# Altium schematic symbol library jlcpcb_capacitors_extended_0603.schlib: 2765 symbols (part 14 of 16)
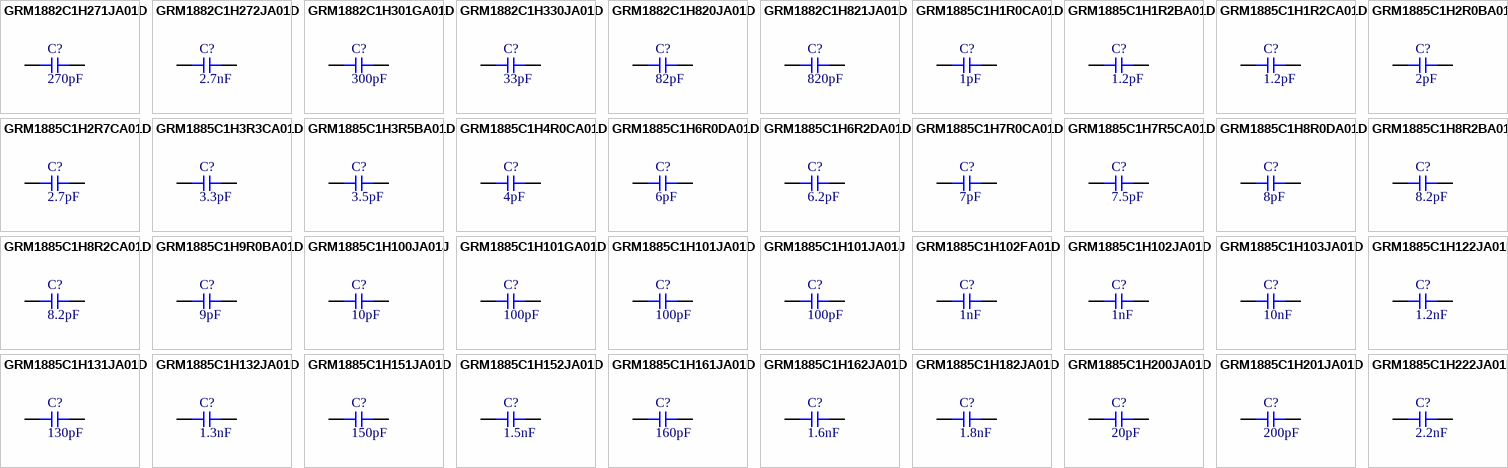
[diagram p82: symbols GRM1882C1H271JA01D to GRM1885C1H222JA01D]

## GRM1885C1H8R0DA01D
designator C?  Capacitance: 8pF  (hidden comment: *)
Capacitor, Ceramic (MLCC), 8pF, ±0.5pF, 50V, C0G, ±0.5pF, SMD 0603; Manufacturer: Murata Electronics; Manufacturer Part Number: GRM1885C1H8R0DA01D
footprint CAP-0603 (0603 (1608M) Capacitor)
pins: 1, 2

## GRM1885C1H8R2BA01D
designator C?  Capacitance: 8.2pF  (hidden comment: *)
Capacitor, Ceramic (MLCC), 8.2pF, ±0.1pF, 50V, ±0.1pF, SMD 0603; Manufacturer: Murata Electronics; Manufacturer Part Number: GRM1885C1H8R2BA01D
footprint CAP-0603 (0603 (1608M) Capacitor)
pins: 1, 2

## GRM1885C1H8R2CA01D
designator C?  Capacitance: 8.2pF  (hidden comment: *)
Capacitor, Ceramic (MLCC), 8.2pF, ±0.25pF, 50V, C0G, ±0.25pF, SMD 0603; Manufacturer: Murata Electronics; Manufacturer Part Number: GRM1885C1H8R2CA01D
footprint CAP-0603 (0603 (1608M) Capacitor)
pins: 1, 2

## GRM1885C1H9R0BA01D
designator C?  Capacitance: 9pF  (hidden comment: *)
Capacitor, Ceramic (MLCC), 9pF, ±0.1pF, 50V, C0G, ±0.1pF, SMD 0603; Manufacturer: Murata Electronics; Manufacturer Part Number: GRM1885C1H9R0BA01D
footprint CAP-0603 (0603 (1608M) Capacitor)
pins: 1, 2

## GRM1885C1H100JA01J
designator C?  Capacitance: 10pF  (hidden comment: *)
Capacitor, Ceramic (MLCC), 10pF, ±5%, 50V, C0G, ±5%, SMD 0603; Manufacturer: Murata Electronics; Manufacturer Part Number: GRM1885C1H100JA01J
footprint CAP-0603 (0603 (1608M) Capacitor)
pins: 1, 2

## GRM1885C1H101GA01D
designator C?  Capacitance: 100pF  (hidden comment: *)
Capacitor, Ceramic (MLCC), 100pF, ±2%, ±2%, SMD 0603; Manufacturer: Murata Electronics; Manufacturer Part Number: GRM1885C1H101GA01D
footprint CAP-0603 (0603 (1608M) Capacitor)
pins: 1, 2

## GRM1885C1H101JA01D
designator C?  Capacitance: 100pF  (hidden comment: *)
Capacitor, Ceramic (MLCC), 100pF, ±5%, 50V, C0G, ±5%, SMD 0603; Manufacturer: Murata Electronics; Manufacturer Part Number: GRM1885C1H101JA01D
footprint CAP-0603 (0603 (1608M) Capacitor)
pins: 1, 2

## GRM1885C1H101JA01J
designator C?  Capacitance: 100pF  (hidden comment: *)
Capacitor, Ceramic (MLCC), 100pF, ±5%, 50V, C0G, ±5%, SMD 0603; Manufacturer: Murata Electronics; Manufacturer Part Number: GRM1885C1H101JA01J
footprint CAP-0603 (0603 (1608M) Capacitor)
pins: 1, 2

## GRM1885C1H102FA01D
designator C?  Capacitance: 1nF  (hidden comment: *)
Capacitor, Ceramic (MLCC), 1nF, ±1%, ±1%, SMD 0603; Manufacturer: Murata Electronics; Manufacturer Part Number: GRM1885C1H102FA01D
footprint CAP-0603 (0603 (1608M) Capacitor)
pins: 1, 2

## GRM1885C1H102JA01D
designator C?  Capacitance: 1nF  (hidden comment: *)
Capacitor, Ceramic (MLCC), 1nF, ±5%, 50V, C0G, ±5%, SMD 0603; Manufacturer: Murata Electronics; Manufacturer Part Number: GRM1885C1H102JA01D
footprint CAP-0603 (0603 (1608M) Capacitor)
pins: 1, 2

## GRM1885C1H103JA01D
designator C?  Capacitance: 10nF  (hidden comment: *)
Capacitor, Ceramic (MLCC), 10nF, ±5%, 50V, C0G, ±5%, SMD 0603; Manufacturer: Murata Electronics; Manufacturer Part Number: GRM1885C1H103JA01D
footprint CAP-0603 (0603 (1608M) Capacitor)
pins: 1, 2

## GRM1885C1H122JA01D
designator C?  Capacitance: 1.2nF  (hidden comment: *)
Capacitor, Ceramic (MLCC), 1.2nF, ±5%, 50V, C0G, ±5%, SMD 0603; Manufacturer: Murata Electronics; Manufacturer Part Number: GRM1885C1H122JA01D
footprint CAP-0603 (0603 (1608M) Capacitor)
pins: 1, 2

## GRM1885C1H131JA01D
designator C?  Capacitance: 130pF  (hidden comment: *)
Capacitor, Ceramic (MLCC), 130pF, ±5%, 50V, C0G, ±5%, SMD 0603; Manufacturer: Murata Electronics; Manufacturer Part Number: GRM1885C1H131JA01D
footprint CAP-0603 (0603 (1608M) Capacitor)
pins: 1, 2

## GRM1885C1H132JA01D
designator C?  Capacitance: 1.3nF  (hidden comment: *)
Capacitor, Ceramic (MLCC), 1.3nF, ±5%, 50V, ±5%, SMD 0603; Manufacturer: Murata Electronics; Manufacturer Part Number: GRM1885C1H132JA01D
footprint CAP-0603 (0603 (1608M) Capacitor)
pins: 1, 2

## GRM1885C1H151JA01D
designator C?  Capacitance: 150pF  (hidden comment: *)
Capacitor, Ceramic (MLCC), 150pF, ±5%, 50V, C0G, ±5%, SMD 0603; Manufacturer: Murata Electronics; Manufacturer Part Number: GRM1885C1H151JA01D
footprint CAP-0603 (0603 (1608M) Capacitor)
pins: 1, 2

## GRM1885C1H152JA01D
designator C?  Capacitance: 1.5nF  (hidden comment: *)
Capacitor, Ceramic (MLCC), 1.5nF, ±5%, 50V, C0G, ±5%, SMD 0603; Manufacturer: Murata Electronics; Manufacturer Part Number: GRM1885C1H152JA01D
footprint CAP-0603 (0603 (1608M) Capacitor)
pins: 1, 2

## GRM1885C1H161JA01D
designator C?  Capacitance: 160pF  (hidden comment: *)
Capacitor, Ceramic (MLCC), 160pF, ±5%, ±5%, SMD 0603; Manufacturer: Murata Electronics; Manufacturer Part Number: GRM1885C1H161JA01D
footprint CAP-0603 (0603 (1608M) Capacitor)
pins: 1, 2

## GRM1885C1H162JA01D
designator C?  Capacitance: 1.6nF  (hidden comment: *)
Capacitor, Ceramic (MLCC), 1.6nF, ±5%, 50V, C0G, ±5%, SMD 0603; Manufacturer: Murata Electronics; Manufacturer Part Number: GRM1885C1H162JA01D
footprint CAP-0603 (0603 (1608M) Capacitor)
pins: 1, 2

## GRM1885C1H182JA01D
designator C?  Capacitance: 1.8nF  (hidden comment: *)
Capacitor, Ceramic (MLCC), 1.8nF, ±5%, 50V, C0G, ±5%, SMD 0603; Manufacturer: Murata Electronics; Manufacturer Part Number: GRM1885C1H182JA01D
footprint CAP-0603 (0603 (1608M) Capacitor)
pins: 1, 2

## GRM1885C1H200JA01D
designator C?  Capacitance: 20pF  (hidden comment: *)
Capacitor, Ceramic (MLCC), 20pF, ±5%, 50V, C0G, ±5%, SMD 0603; Manufacturer: Murata Electronics; Manufacturer Part Number: GRM1885C1H200JA01D
footprint CAP-0603 (0603 (1608M) Capacitor)
pins: 1, 2

## GRM1885C1H201JA01D
designator C?  Capacitance: 200pF  (hidden comment: *)
Capacitor, Ceramic (MLCC), 200pF, ±5%, 50V, C0G, ±5%, SMD 0603; Manufacturer: Murata Electronics; Manufacturer Part Number: GRM1885C1H201JA01D
footprint CAP-0603 (0603 (1608M) Capacitor)
pins: 1, 2

## GRM1885C1H222JA01D
designator C?  Capacitance: 2.2nF  (hidden comment: *)
Capacitor, Ceramic (MLCC), 2.2nF, ±5%, 50V, C0G, ±5%, SMD 0603; Manufacturer: Murata Electronics; Manufacturer Part Number: GRM1885C1H222JA01D
footprint CAP-0603 (0603 (1608M) Capacitor)
pins: 1, 2

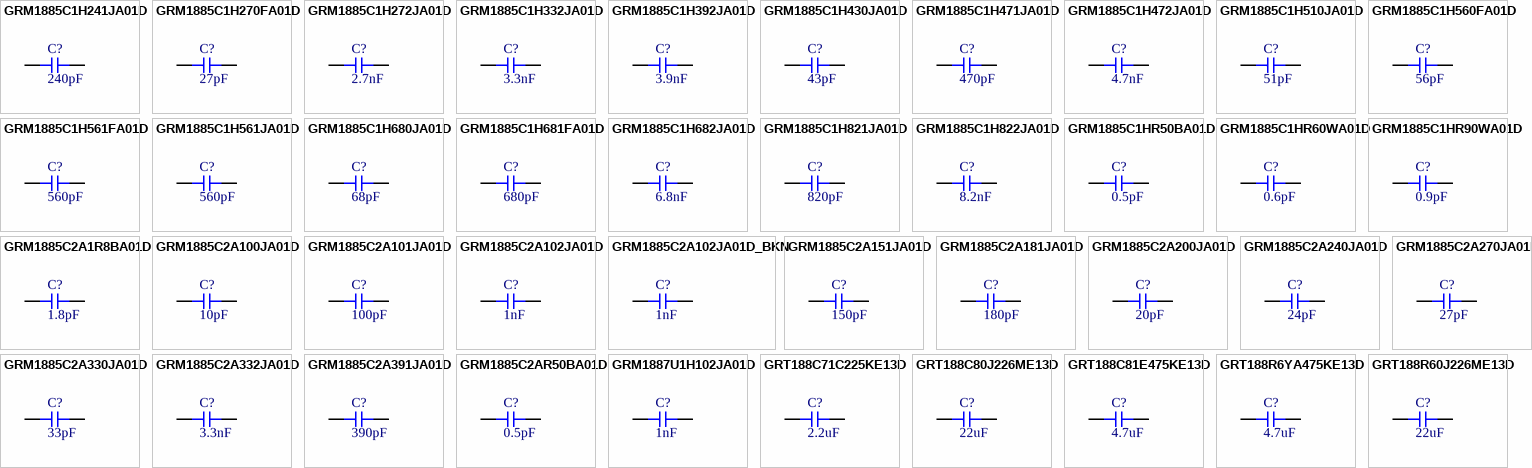
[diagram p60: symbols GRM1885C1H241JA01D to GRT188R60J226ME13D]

## GRM1885C1H241JA01D
designator C?  Capacitance: 240pF  (hidden comment: *)
Capacitor, Ceramic (MLCC), 240pF, ±5%, 50V, C0G, ±5%, SMD 0603; Manufacturer: Murata Electronics; Manufacturer Part Number: GRM1885C1H241JA01D
footprint CAP-0603 (0603 (1608M) Capacitor)
pins: 1, 2

## GRM1885C1H270FA01D
designator C?  Capacitance: 27pF  (hidden comment: *)
Capacitor, Ceramic (MLCC), 27pF, ±1%, 50V, C0G, ±1%, SMD 0603; Manufacturer: Murata Electronics; Manufacturer Part Number: GRM1885C1H270FA01D
footprint CAP-0603 (0603 (1608M) Capacitor)
pins: 1, 2

## GRM1885C1H272JA01D
designator C?  Capacitance: 2.7nF  (hidden comment: *)
Capacitor, Ceramic (MLCC), 2.7nF, ±5%, 50V, C0G, ±5%, SMD 0603; Manufacturer: Murata Electronics; Manufacturer Part Number: GRM1885C1H272JA01D
footprint CAP-0603 (0603 (1608M) Capacitor)
pins: 1, 2

## GRM1885C1H332JA01D
designator C?  Capacitance: 3.3nF  (hidden comment: *)
Capacitor, Ceramic (MLCC), 3.3nF, ±5%, 50V, C0G, ±5%, SMD 0603; Manufacturer: Murata Electronics; Manufacturer Part Number: GRM1885C1H332JA01D
footprint CAP-0603 (0603 (1608M) Capacitor)
pins: 1, 2

## GRM1885C1H392JA01D
designator C?  Capacitance: 3.9nF  (hidden comment: *)
Capacitor, Ceramic (MLCC), 3.9nF, ±5%, 50V, C0G, ±5%, SMD 0603; Manufacturer: Murata Electronics; Manufacturer Part Number: GRM1885C1H392JA01D
footprint CAP-0603 (0603 (1608M) Capacitor)
pins: 1, 2

## GRM1885C1H430JA01D
designator C?  Capacitance: 43pF  (hidden comment: *)
Capacitor, Ceramic (MLCC), 43pF, ±5%, 50V, C0G, ±5%, SMD 0603; Manufacturer: Murata Electronics; Manufacturer Part Number: GRM1885C1H430JA01D
footprint CAP-0603 (0603 (1608M) Capacitor)
pins: 1, 2

## GRM1885C1H471JA01D
designator C?  Capacitance: 470pF  (hidden comment: *)
Capacitor, Ceramic (MLCC), 470pF, ±5%, 50V, C0G, ±5%, SMD 0603; Manufacturer: Murata Electronics; Manufacturer Part Number: GRM1885C1H471JA01D
footprint CAP-0603 (0603 (1608M) Capacitor)
pins: 1, 2

## GRM1885C1H472JA01D
designator C?  Capacitance: 4.7nF  (hidden comment: *)
Capacitor, Ceramic (MLCC), 4.7nF, ±5%, 50V, C0G, ±5%, SMD 0603; Manufacturer: Murata Electronics; Manufacturer Part Number: GRM1885C1H472JA01D
footprint CAP-0603 (0603 (1608M) Capacitor)
pins: 1, 2

## GRM1885C1H510JA01D
designator C?  Capacitance: 51pF  (hidden comment: *)
Capacitor, Ceramic (MLCC), 51pF, ±5%, 50V, C0G, ±5%, SMD 0603; Manufacturer: Murata Electronics; Manufacturer Part Number: GRM1885C1H510JA01D
footprint CAP-0603 (0603 (1608M) Capacitor)
pins: 1, 2

## GRM1885C1H560FA01D
designator C?  Capacitance: 56pF  (hidden comment: *)
Capacitor, Ceramic (MLCC), 56pF, ±1%, 50V, C0G, ±1%, SMD 0603; Manufacturer: Murata Electronics; Manufacturer Part Number: GRM1885C1H560FA01D
footprint CAP-0603 (0603 (1608M) Capacitor)
pins: 1, 2

## GRM1885C1H561FA01D
designator C?  Capacitance: 560pF  (hidden comment: *)
Capacitor, Ceramic (MLCC), 560pF, ±1%, 50V, C0G, ±1%, SMD 0603; Manufacturer: Murata Electronics; Manufacturer Part Number: GRM1885C1H561FA01D
footprint CAP-0603 (0603 (1608M) Capacitor)
pins: 1, 2

## GRM1885C1H561JA01D
designator C?  Capacitance: 560pF  (hidden comment: *)
Capacitor, Ceramic (MLCC), 560pF, ±5%, 50V, C0G, ±5%, SMD 0603; Manufacturer: Murata Electronics; Manufacturer Part Number: GRM1885C1H561JA01D
footprint CAP-0603 (0603 (1608M) Capacitor)
pins: 1, 2

## GRM1885C1H680JA01D
designator C?  Capacitance: 68pF  (hidden comment: *)
Capacitor, Ceramic (MLCC), 68pF, ±5%, 50V, C0G, ±5%, SMD 0603; Manufacturer: Murata Electronics; Manufacturer Part Number: GRM1885C1H680JA01D
footprint CAP-0603 (0603 (1608M) Capacitor)
pins: 1, 2

## GRM1885C1H681FA01D
designator C?  Capacitance: 680pF  (hidden comment: *)
Capacitor, Ceramic (MLCC), 680pF, ±1%, 50V, C0G, ±1%, SMD 0603; Manufacturer: Murata Electronics; Manufacturer Part Number: GRM1885C1H681FA01D
footprint CAP-0603 (0603 (1608M) Capacitor)
pins: 1, 2

## GRM1885C1H682JA01D
designator C?  Capacitance: 6.8nF  (hidden comment: *)
Capacitor, Ceramic (MLCC), 6.8nF, ±5%, 50V, C0G, ±5%, SMD 0603; Manufacturer: Murata Electronics; Manufacturer Part Number: GRM1885C1H682JA01D
footprint CAP-0603 (0603 (1608M) Capacitor)
pins: 1, 2

## GRM1885C1H821JA01D
designator C?  Capacitance: 820pF  (hidden comment: *)
Capacitor, Ceramic (MLCC), 820pF, ±5%, 50V, C0G, ±5%, SMD 0603; Manufacturer: Murata Electronics; Manufacturer Part Number: GRM1885C1H821JA01D
footprint CAP-0603 (0603 (1608M) Capacitor)
pins: 1, 2

## GRM1885C1H822JA01D
designator C?  Capacitance: 8.2nF  (hidden comment: *)
Capacitor, Ceramic (MLCC), 8.2nF, ±5%, 50V, ±5%, SMD 0603; Manufacturer: Murata Electronics; Manufacturer Part Number: GRM1885C1H822JA01D
footprint CAP-0603 (0603 (1608M) Capacitor)
pins: 1, 2

## GRM1885C1HR50BA01D
designator C?  Capacitance: 0.5pF  (hidden comment: *)
Capacitor, Ceramic (MLCC), 0.5pF, ±0.1pF, 50V, C0G, ±0.1pF, SMD 0603; Manufacturer: Murata Electronics; Manufacturer Part Number: GRM1885C1HR50BA01D
footprint CAP-0603 (0603 (1608M) Capacitor)
pins: 1, 2

## GRM1885C1HR60WA01D
designator C?  Capacitance: 0.6pF  (hidden comment: *)
Capacitor, Ceramic (MLCC), 0.6pF, ±0.05pF, 50V, C0G, ±0.05pF, SMD 0603; Manufacturer: Murata Electronics; Manufacturer Part Number: GRM1885C1HR60WA01D
footprint CAP-0603 (0603 (1608M) Capacitor)
pins: 1, 2

## GRM1885C1HR90WA01D
designator C?  Capacitance: 0.9pF  (hidden comment: *)
Capacitor, Ceramic (MLCC), 0.9pF, ±0.05pF, 50V, C0G, ±0.05pF, SMD 0603; Manufacturer: Murata Electronics; Manufacturer Part Number: GRM1885C1HR90WA01D
footprint CAP-0603 (0603 (1608M) Capacitor)
pins: 1, 2

## GRM1885C2A1R8BA01D
designator C?  Capacitance: 1.8pF  (hidden comment: *)
Capacitor, Ceramic (MLCC), 1.8pF, ±0.1pF, 100V, C0G, ±0.1pF, SMD 0603; Manufacturer: Murata Electronics; Manufacturer Part Number: GRM1885C2A1R8BA01D
footprint CAP-0603 (0603 (1608M) Capacitor)
pins: 1, 2

## GRM1885C2A100JA01D
designator C?  Capacitance: 10pF  (hidden comment: *)
Capacitor, Ceramic (MLCC), 10pF, ±5%, ±5%, SMD 0603; Manufacturer: Murata Electronics; Manufacturer Part Number: GRM1885C2A100JA01D
footprint CAP-0603 (0603 (1608M) Capacitor)
pins: 1, 2

## GRM1885C2A101JA01D
designator C?  Capacitance: 100pF  (hidden comment: *)
Capacitor, Ceramic (MLCC), 100pF, ±5%, 100V, C0G, ±5%, SMD 0603; Manufacturer: Murata Electronics; Manufacturer Part Number: GRM1885C2A101JA01D
footprint CAP-0603 (0603 (1608M) Capacitor)
pins: 1, 2

## GRM1885C2A102JA01D
designator C?  Capacitance: 1nF  (hidden comment: *)
Capacitor, Ceramic (MLCC), 1nF, ±5%, 100V, C0G, ±5%, SMD 0603; Manufacturer: Murata Electronics; Manufacturer Part Number: GRM1885C2A102JA01D
footprint CAP-0603 (0603 (1608M) Capacitor)
pins: 1, 2

## GRM1885C2A102JA01D_BKN
designator C?  Capacitance: 1nF  (hidden comment: *)
Capacitor, Ceramic (MLCC), 1nF, ±5%, 100V, C0G, ±5%, SMD 0603; Manufacturer: Murata Electronics; Manufacturer Part Number: GRM1885C2A102JA01D/BKN
footprint CAP-0603 (0603 (1608M) Capacitor)
pins: 1, 2

## GRM1885C2A151JA01D
designator C?  Capacitance: 150pF  (hidden comment: *)
Capacitor, Ceramic (MLCC), 150pF, ±5%, 100V, C0G, ±5%, SMD 0603; Manufacturer: Murata Electronics; Manufacturer Part Number: GRM1885C2A151JA01D
footprint CAP-0603 (0603 (1608M) Capacitor)
pins: 1, 2

## GRM1885C2A181JA01D
designator C?  Capacitance: 180pF  (hidden comment: *)
Capacitor, Ceramic (MLCC), 180pF, ±5%, ±5%, SMD 0603; Manufacturer: Murata Electronics; Manufacturer Part Number: GRM1885C2A181JA01D
footprint CAP-0603 (0603 (1608M) Capacitor)
pins: 1, 2

## GRM1885C2A200JA01D
designator C?  Capacitance: 20pF  (hidden comment: *)
Capacitor, Ceramic (MLCC), 20pF, ±5%, ±5%, SMD 0603; Manufacturer: Murata Electronics; Manufacturer Part Number: GRM1885C2A200JA01D
footprint CAP-0603 (0603 (1608M) Capacitor)
pins: 1, 2

## GRM1885C2A240JA01D
designator C?  Capacitance: 24pF  (hidden comment: *)
Capacitor, Ceramic (MLCC), 24pF, ±5%, 100V, C0G, ±5%, SMD 0603; Manufacturer: Murata Electronics; Manufacturer Part Number: GRM1885C2A240JA01D
footprint CAP-0603 (0603 (1608M) Capacitor)
pins: 1, 2

## GRM1885C2A270JA01D
designator C?  Capacitance: 27pF  (hidden comment: *)
Capacitor, Ceramic (MLCC), 27pF, ±5%, 100V, C0G, ±5%, SMD 0603; Manufacturer: Murata Electronics; Manufacturer Part Number: GRM1885C2A270JA01D
footprint CAP-0603 (0603 (1608M) Capacitor)
pins: 1, 2

## GRM1885C2A330JA01D
designator C?  Capacitance: 33pF  (hidden comment: *)
Capacitor, Ceramic (MLCC), 33pF, ±5%, 100V, C0G, ±5%, SMD 0603; Manufacturer: Murata Electronics; Manufacturer Part Number: GRM1885C2A330JA01D
footprint CAP-0603 (0603 (1608M) Capacitor)
pins: 1, 2

## GRM1885C2A332JA01D
designator C?  Capacitance: 3.3nF  (hidden comment: *)
Capacitor, Ceramic (MLCC), 3.3nF, ±5%, 100V, X7R, ±5%, SMD 0603; Manufacturer: Murata Electronics; Manufacturer Part Number: GRM1885C2A332JA01D
footprint CAP-0603 (0603 (1608M) Capacitor)
pins: 1, 2

## GRM1885C2A391JA01D
designator C?  Capacitance: 390pF  (hidden comment: *)
Capacitor, Ceramic (MLCC), 390pF, ±5%, 100V, C0G, ±5%, SMD 0603; Manufacturer: Murata Electronics; Manufacturer Part Number: GRM1885C2A391JA01D
footprint CAP-0603 (0603 (1608M) Capacitor)
pins: 1, 2

## GRM1885C2AR50BA01D
designator C?  Capacitance: 0.5pF  (hidden comment: *)
Capacitor, Ceramic (MLCC), 0.5pF, ±0.1pF, 100V, C0G, ±0.1pF, SMD 0603; Manufacturer: Murata Electronics; Manufacturer Part Number: GRM1885C2AR50BA01D
footprint CAP-0603 (0603 (1608M) Capacitor)
pins: 1, 2

## GRM1887U1H102JA01D
designator C?  Capacitance: 1nF  (hidden comment: *)
Capacitor, Ceramic (MLCC), 1nF, ±5%, 50V, U2J, ±5%, SMD 0603; Manufacturer: Murata Electronics; Manufacturer Part Number: GRM1887U1H102JA01D
footprint CAP-0603 (0603 (1608M) Capacitor)
pins: 1, 2

## GRT188C71C225KE13D
designator C?  Capacitance: 2.2uF  (hidden comment: *)
Capacitor, Ceramic (MLCC), 2.2uF, ±10%, ±10%, SMD 0603; Manufacturer: Murata Electronics; Manufacturer Part Number: GRT188C71C225KE13D
footprint CAP-0603 (0603 (1608M) Capacitor)
pins: 1, 2

## GRT188C80J226ME13D
designator C?  Capacitance: 22uF  (hidden comment: *)
Capacitor, Ceramic (MLCC), 22uF, ±20%, 6.3V, -55°C ~ 105°C, ±20%, SMD 0603; Manufacturer: Murata Electronics; Manufacturer Part Number: GRT188C80J226ME13D
footprint CAP-0603 (0603 (1608M) Capacitor)
pins: 1, 2

## GRT188C81E475KE13D
designator C?  Capacitance: 4.7uF  (hidden comment: *)
Capacitor, Ceramic (MLCC), 4.7uF, ±10%, ±10%, SMD 0603; Manufacturer: Murata Electronics; Manufacturer Part Number: GRT188C81E475KE13D
footprint CAP-0603 (0603 (1608M) Capacitor)
pins: 1, 2

## GRT188R6YA475KE13D
designator C?  Capacitance: 4.7uF  (hidden comment: *)
Capacitor, Ceramic (MLCC), 4.7uF, ±10%, 35V, X5R, ±10%, SMD 0603; Manufacturer: Murata Electronics; Manufacturer Part Number: GRT188R6YA475KE13D
footprint CAP-0603 (0603 (1608M) Capacitor)
pins: 1, 2

## GRT188R60J226ME13D
designator C?  Capacitance: 22uF  (hidden comment: *)
Capacitor, Ceramic (MLCC), 22uF, ±20%, 6.3V, X5R, ±20%, SMD 0603; Manufacturer: Murata Electronics; Manufacturer Part Number: GRT188R60J226ME13D
footprint CAP-0603 (0603 (1608M) Capacitor)
pins: 1, 2

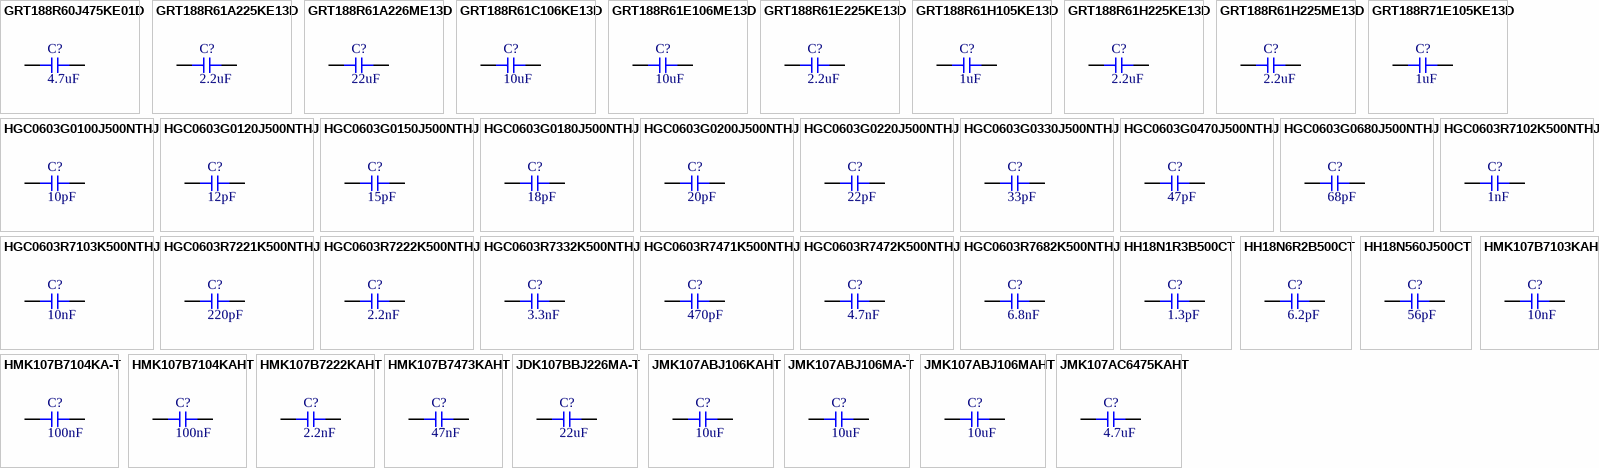
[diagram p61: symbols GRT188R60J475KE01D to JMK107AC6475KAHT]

## GRT188R60J475KE01D
designator C?  Capacitance: 4.7uF  (hidden comment: *)
Capacitor, Ceramic (MLCC), 4.7uF, ±10%, 6.3V, X5R, ±10%, SMD 0603; Manufacturer: Murata Electronics; Manufacturer Part Number: GRT188R60J475KE01D
footprint CAP-0603 (0603 (1608M) Capacitor)
pins: 1, 2

## GRT188R61A225KE13D
designator C?  Capacitance: 2.2uF  (hidden comment: *)
Capacitor, Ceramic (MLCC), 2.2uF, ±10%, 10V, X5R, ±10%, SMD 0603; Manufacturer: Murata Electronics; Manufacturer Part Number: GRT188R61A225KE13D
footprint CAP-0603 (0603 (1608M) Capacitor)
pins: 1, 2

## GRT188R61A226ME13D
designator C?  Capacitance: 22uF  (hidden comment: *)
Capacitor, Ceramic (MLCC), 22uF, ±20%, 10V, X5R, ±20%, SMD 0603; Manufacturer: Murata Electronics; Manufacturer Part Number: GRT188R61A226ME13D
footprint CAP-0603 (0603 (1608M) Capacitor)
pins: 1, 2

## GRT188R61C106KE13D
designator C?  Capacitance: 10uF  (hidden comment: *)
Capacitor, Ceramic (MLCC), 10uF, ±10%, ±10%, SMD 0603; Manufacturer: Murata Electronics; Manufacturer Part Number: GRT188R61C106KE13D
footprint CAP-0603 (0603 (1608M) Capacitor)
pins: 1, 2

## GRT188R61E106ME13D
designator C?  Capacitance: 10uF  (hidden comment: *)
Capacitor, Ceramic (MLCC), 10uF, ±20%, 25V, X5R, ±20%, SMD 0603; Manufacturer: Murata Electronics; Manufacturer Part Number: GRT188R61E106ME13D
footprint CAP-0603 (0603 (1608M) Capacitor)
pins: 1, 2

## GRT188R61E225KE13D
designator C?  Capacitance: 2.2uF  (hidden comment: *)
Capacitor, Ceramic (MLCC), 2.2uF, ±10%, ±10%, SMD 0603; Manufacturer: Murata Electronics; Manufacturer Part Number: GRT188R61E225KE13D
footprint CAP-0603 (0603 (1608M) Capacitor)
pins: 1, 2

## GRT188R61H105KE13D
designator C?  Capacitance: 1uF  (hidden comment: *)
Capacitor, Ceramic (MLCC), 1uF, ±10%, 50V, X5R, ±10%, SMD 0603; Manufacturer: Murata Electronics; Manufacturer Part Number: GRT188R61H105KE13D
footprint CAP-0603 (0603 (1608M) Capacitor)
pins: 1, 2

## GRT188R61H225KE13D
designator C?  Capacitance: 2.2uF  (hidden comment: *)
Capacitor, Ceramic (MLCC), 2.2uF, ±10%, ±10%, SMD 0603; Manufacturer: Murata Electronics; Manufacturer Part Number: GRT188R61H225KE13D
footprint CAP-0603 (0603 (1608M) Capacitor)
pins: 1, 2

## GRT188R61H225ME13D
designator C?  Capacitance: 2.2uF  (hidden comment: *)
Capacitor, Ceramic (MLCC), 2.2uF, ±20%, 50V, X5R, ±20%, SMD 0603; Manufacturer: Murata Electronics; Manufacturer Part Number: GRT188R61H225ME13D
footprint CAP-0603 (0603 (1608M) Capacitor)
pins: 1, 2

## GRT188R71E105KE13D
designator C?  Capacitance: 1uF  (hidden comment: *)
Capacitor, Ceramic (MLCC), 1uF, ±10%, ±10%, SMD 0603; Manufacturer: Murata Electronics; Manufacturer Part Number: GRT188R71E105KE13D
footprint CAP-0603 (0603 (1608M) Capacitor)
pins: 1, 2

## HGC0603G0100J500NTHJ
designator C?  Capacitance: 10pF  (hidden comment: *)
Capacitor, Ceramic (MLCC), 10pF, ±5%, 50V, C0G, ±5%, SMD 0603; Manufacturer: Chinocera; Manufacturer Part Number: HGC0603G0100J500NTHJ
footprint CAP-0603 (0603 (1608M) Capacitor)
pins: 1, 2

## HGC0603G0120J500NTHJ
designator C?  Capacitance: 12pF  (hidden comment: *)
Capacitor, Ceramic (MLCC), 12pF, ±5%, 50V, C0G, ±5%, SMD 0603; Manufacturer: Chinocera; Manufacturer Part Number: HGC0603G0120J500NTHJ
footprint CAP-0603 (0603 (1608M) Capacitor)
pins: 1, 2

## HGC0603G0150J500NTHJ
designator C?  Capacitance: 15pF  (hidden comment: *)
Capacitor, Ceramic (MLCC), 15pF, ±5%, 50V, C0G, ±5%, SMD 0603; Manufacturer: Chinocera; Manufacturer Part Number: HGC0603G0150J500NTHJ
footprint CAP-0603 (0603 (1608M) Capacitor)
pins: 1, 2

## HGC0603G0180J500NTHJ
designator C?  Capacitance: 18pF  (hidden comment: *)
Capacitor, Ceramic (MLCC), 18pF, ±5%, 50V, C0G, ±5%, SMD 0603; Manufacturer: Chinocera; Manufacturer Part Number: HGC0603G0180J500NTHJ
footprint CAP-0603 (0603 (1608M) Capacitor)
pins: 1, 2

## HGC0603G0200J500NTHJ
designator C?  Capacitance: 20pF  (hidden comment: *)
Capacitor, Ceramic (MLCC), 20pF, ±5%, 50V, C0G, ±5%, SMD 0603; Manufacturer: Chinocera; Manufacturer Part Number: HGC0603G0200J500NTHJ
footprint CAP-0603 (0603 (1608M) Capacitor)
pins: 1, 2

## HGC0603G0220J500NTHJ
designator C?  Capacitance: 22pF  (hidden comment: *)
Capacitor, Ceramic (MLCC), 22pF, ±5%, 50V, C0G, ±5%, SMD 0603; Manufacturer: Chinocera; Manufacturer Part Number: HGC0603G0220J500NTHJ
footprint CAP-0603 (0603 (1608M) Capacitor)
pins: 1, 2

## HGC0603G0330J500NTHJ
designator C?  Capacitance: 33pF  (hidden comment: *)
Capacitor, Ceramic (MLCC), 33pF, ±5%, 50V, C0G, ±5%, SMD 0603; Manufacturer: Chinocera; Manufacturer Part Number: HGC0603G0330J500NTHJ
footprint CAP-0603 (0603 (1608M) Capacitor)
pins: 1, 2

## HGC0603G0470J500NTHJ
designator C?  Capacitance: 47pF  (hidden comment: *)
Capacitor, Ceramic (MLCC), 47pF, ±5%, 50V, C0G, ±5%, SMD 0603; Manufacturer: Chinocera; Manufacturer Part Number: HGC0603G0470J500NTHJ
footprint CAP-0603 (0603 (1608M) Capacitor)
pins: 1, 2

## HGC0603G0680J500NTHJ
designator C?  Capacitance: 68pF  (hidden comment: *)
Capacitor, Ceramic (MLCC), 68pF, ±5%, 50V, C0G, ±5%, SMD 0603; Manufacturer: Chinocera; Manufacturer Part Number: HGC0603G0680J500NTHJ
footprint CAP-0603 (0603 (1608M) Capacitor)
pins: 1, 2

## HGC0603R7102K500NTHJ
designator C?  Capacitance: 1nF  (hidden comment: *)
Capacitor, Ceramic (MLCC), 1nF, ±10%, 50V, X7R, ±10%, SMD 0603; Manufacturer: Chinocera; Manufacturer Part Number: HGC0603R7102K500NTHJ
footprint CAP-0603 (0603 (1608M) Capacitor)
pins: 1, 2

## HGC0603R7103K500NTHJ
designator C?  Capacitance: 10nF  (hidden comment: *)
Capacitor, Ceramic (MLCC), 10nF, ±10%, 50V, X7R, ±10%, SMD 0603; Manufacturer: Chinocera; Manufacturer Part Number: HGC0603R7103K500NTHJ
footprint CAP-0603 (0603 (1608M) Capacitor)
pins: 1, 2

## HGC0603R7221K500NTHJ
designator C?  Capacitance: 220pF  (hidden comment: *)
Capacitor, Ceramic (MLCC), 220pF, ±10%, 50V, X7R, ±10%, SMD 0603; Manufacturer: Chinocera; Manufacturer Part Number: HGC0603R7221K500NTHJ
footprint CAP-0603 (0603 (1608M) Capacitor)
pins: 1, 2

## HGC0603R7222K500NTHJ
designator C?  Capacitance: 2.2nF  (hidden comment: *)
Capacitor, Ceramic (MLCC), 2.2nF, ±10%, 50V, X7R, ±10%, SMD 0603; Manufacturer: Chinocera; Manufacturer Part Number: HGC0603R7222K500NTHJ
footprint CAP-0603 (0603 (1608M) Capacitor)
pins: 1, 2

## HGC0603R7332K500NTHJ
designator C?  Capacitance: 3.3nF  (hidden comment: *)
Capacitor, Ceramic (MLCC), 3.3nF, ±10%, 50V, X7R, ±10%, SMD 0603; Manufacturer: Chinocera; Manufacturer Part Number: HGC0603R7332K500NTHJ
footprint CAP-0603 (0603 (1608M) Capacitor)
pins: 1, 2

## HGC0603R7471K500NTHJ
designator C?  Capacitance: 470pF  (hidden comment: *)
Capacitor, Ceramic (MLCC), 470pF, ±10%, 50V, X7R, ±10%, SMD 0603; Manufacturer: Chinocera; Manufacturer Part Number: HGC0603R7471K500NTHJ
footprint CAP-0603 (0603 (1608M) Capacitor)
pins: 1, 2

## HGC0603R7472K500NTHJ
designator C?  Capacitance: 4.7nF  (hidden comment: *)
Capacitor, Ceramic (MLCC), 4.7nF, ±10%, 50V, X7R, ±10%, SMD 0603; Manufacturer: Chinocera; Manufacturer Part Number: HGC0603R7472K500NTHJ
footprint CAP-0603 (0603 (1608M) Capacitor)
pins: 1, 2

## HGC0603R7682K500NTHJ
designator C?  Capacitance: 6.8nF  (hidden comment: *)
Capacitor, Ceramic (MLCC), 6.8nF, ±10%, 50V, X7R, ±10%, SMD 0603; Manufacturer: Chinocera; Manufacturer Part Number: HGC0603R7682K500NTHJ
footprint CAP-0603 (0603 (1608M) Capacitor)
pins: 1, 2

## HH18N1R3B500CT
designator C?  Capacitance: 1.3pF  (hidden comment: *)
Capacitor, Ceramic (MLCC), 1.3pF, ±0.1pF, 50V, NP0, ±0.1pF, SMD 0603; Manufacturer: Walsin Tech Corp; Manufacturer Part Number: HH18N1R3B500CT
footprint CAP-0603 (0603 (1608M) Capacitor)
pins: 1, 2

## HH18N6R2B500CT
designator C?  Capacitance: 6.2pF  (hidden comment: *)
Capacitor, Ceramic (MLCC), 6.2pF, ±0.1pF, 50V, NP0, ±0.1pF, SMD 0603; Manufacturer: Walsin Tech Corp; Manufacturer Part Number: HH18N6R2B500CT
footprint CAP-0603 (0603 (1608M) Capacitor)
pins: 1, 2

## HH18N560J500CT
designator C?  Capacitance: 56pF  (hidden comment: *)
Capacitor, Ceramic (MLCC), 56pF, ±5%, 50V, NP0, ±5%, SMD 0603; Manufacturer: Walsin Tech Corp; Manufacturer Part Number: HH18N560J500CT
footprint CAP-0603 (0603 (1608M) Capacitor)
pins: 1, 2

## HMK107B7103KAHT
designator C?  Capacitance: 10nF  (hidden comment: *)
Capacitor, Ceramic (MLCC), 10nF, ±10%, 100V, X7R, ±10%, SMD 0603; Manufacturer: Taiyo Yuden; Manufacturer Part Number: HMK107B7103KAHT
footprint CAP-0603 (0603 (1608M) Capacitor)
pins: 1, 2

## HMK107B7104KA-T
designator C?  Capacitance: 100nF  (hidden comment: *)
Capacitor, Ceramic (MLCC), 100nF, ±10%, 100V, X7R, ±10%, SMD 0603; Manufacturer: Taiyo Yuden; Manufacturer Part Number: HMK107B7104KA-T
footprint CAP-0603 (0603 (1608M) Capacitor)
pins: 1, 2

## HMK107B7104KAHT
designator C?  Capacitance: 100nF  (hidden comment: *)
Capacitor, Ceramic (MLCC), 100nF, ±10%, 100V, X7R, ±10%, SMD 0603; Manufacturer: Taiyo Yuden; Manufacturer Part Number: HMK107B7104KAHT
footprint CAP-0603 (0603 (1608M) Capacitor)
pins: 1, 2

## HMK107B7222KAHT
designator C?  Capacitance: 2.2nF  (hidden comment: *)
Capacitor, Ceramic (MLCC), 2.2nF, ±10%, 100V, X7R, ±10%, SMD 0603; Manufacturer: Taiyo Yuden; Manufacturer Part Number: HMK107B7222KAHT
footprint CAP-0603 (0603 (1608M) Capacitor)
pins: 1, 2

## HMK107B7473KAHT
designator C?  Capacitance: 47nF  (hidden comment: *)
Capacitor, Ceramic (MLCC), 47nF, ±10%, 100V, X7R, ±10%, SMD 0603; Manufacturer: Taiyo Yuden; Manufacturer Part Number: HMK107B7473KAHT
footprint CAP-0603 (0603 (1608M) Capacitor)
pins: 1, 2

## JDK107BBJ226MA-T
designator C?  Capacitance: 22uF  (hidden comment: *)
Capacitor, Ceramic (MLCC), 22uF, ±20%, 6.3V, X5R, ±20%, SMD 0603; Manufacturer: Taiyo Yuden; Manufacturer Part Number: JDK107BBJ226MA-T
footprint CAP-0603 (0603 (1608M) Capacitor)
pins: 1, 2

## JMK107ABJ106KAHT
designator C?  Capacitance: 10uF  (hidden comment: *)
Capacitor, Ceramic (MLCC), 10uF, ±10%, 6.3V, X5R, ±10%, SMD 0603; Manufacturer: Taiyo Yuden; Manufacturer Part Number: JMK107ABJ106KAHT
footprint CAP-0603 (0603 (1608M) Capacitor)
pins: 1, 2

## JMK107ABJ106MA-T
designator C?  Capacitance: 10uF  (hidden comment: *)
Capacitor, Ceramic (MLCC), 10uF, ±20%, 6.3V, X5R, ±20%, SMD 0603; Manufacturer: Taiyo Yuden; Manufacturer Part Number: JMK107ABJ106MA-T
footprint CAP-0603 (0603 (1608M) Capacitor)
pins: 1, 2

## JMK107ABJ106MAHT
designator C?  Capacitance: 10uF  (hidden comment: *)
Capacitor, Ceramic (MLCC), 10uF, ±20%, 6.3V, X5R, ±20%, SMD 0603; Manufacturer: Taiyo Yuden; Manufacturer Part Number: JMK107ABJ106MAHT
footprint CAP-0603 (0603 (1608M) Capacitor)
pins: 1, 2

## JMK107AC6475KAHT
designator C?  Capacitance: 4.7uF  (hidden comment: *)
Capacitor, Ceramic (MLCC), 4.7uF, ±10%, 6.3V, ±10%, SMD 0603; Manufacturer: Taiyo Yuden; Manufacturer Part Number: JMK107AC6475KAHT
footprint CAP-0603 (0603 (1608M) Capacitor)
pins: 1, 2

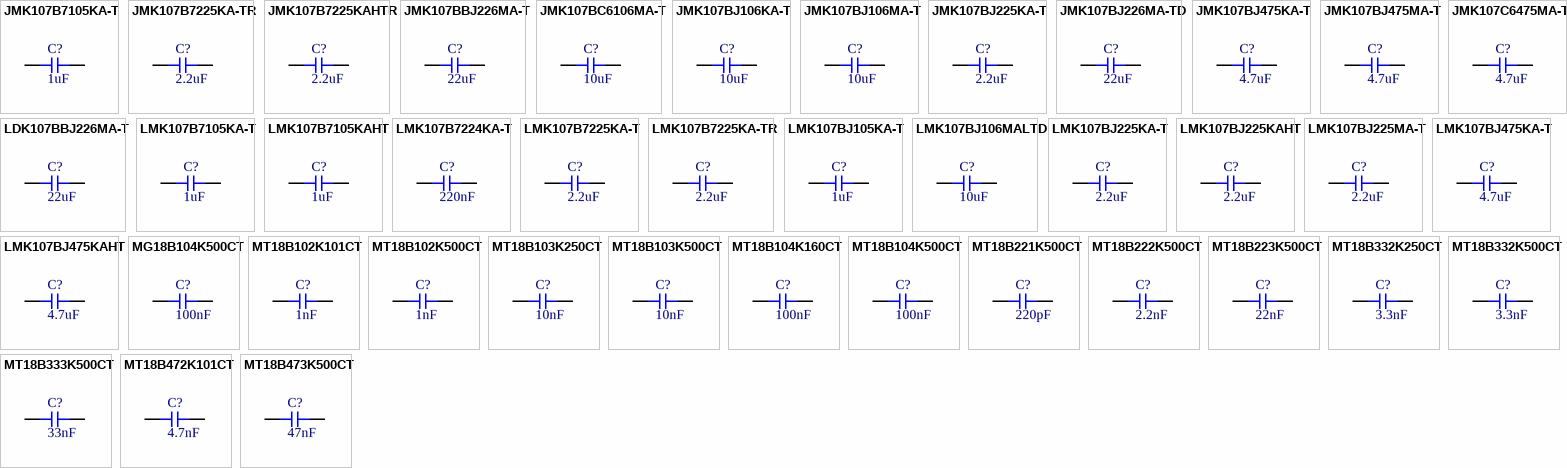
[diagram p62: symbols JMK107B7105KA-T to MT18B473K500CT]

## JMK107B7105KA-T
designator C?  Capacitance: 1uF  (hidden comment: *)
Capacitor, Ceramic (MLCC), 1uF, ±10%, 6.3V, X7R, ±10%, SMD 0603; Manufacturer: Taiyo Yuden; Manufacturer Part Number: JMK107B7105KA-T
footprint CAP-0603 (0603 (1608M) Capacitor)
pins: 1, 2

## JMK107B7225KA-TR
designator C?  Capacitance: 2.2uF  (hidden comment: *)
Capacitor, Ceramic (MLCC), 2.2uF, ±10%, 6.3V, X7R, ±10%, SMD 0603; Manufacturer: Taiyo Yuden; Manufacturer Part Number: JMK107B7225KA-TR
footprint CAP-0603 (0603 (1608M) Capacitor)
pins: 1, 2

## JMK107B7225KAHTR
designator C?  Capacitance: 2.2uF  (hidden comment: *)
Capacitor, Ceramic (MLCC), 2.2uF, ±10%, 6.3V, X7R, ±10%, SMD 0603; Manufacturer: Taiyo Yuden; Manufacturer Part Number: JMK107B7225KAHTR
footprint CAP-0603 (0603 (1608M) Capacitor)
pins: 1, 2

## JMK107BBJ226MA-T
designator C?  Capacitance: 22uF  (hidden comment: *)
Capacitor, Ceramic (MLCC), 22uF, ±20%, 6.3V, X5R, ±20%, SMD 0603; Manufacturer: Taiyo Yuden; Manufacturer Part Number: JMK107BBJ226MA-T
footprint CAP-0603 (0603 (1608M) Capacitor)
pins: 1, 2

## JMK107BC6106MA-T
designator C?  Capacitance: 10uF  (hidden comment: *)
Capacitor, Ceramic (MLCC), 10uF, ±20%, ±20%, SMD 0603; Manufacturer: Taiyo Yuden; Manufacturer Part Number: JMK107BC6106MA-T
footprint CAP-0603 (0603 (1608M) Capacitor)
pins: 1, 2

## JMK107BJ106KA-T
designator C?  Capacitance: 10uF  (hidden comment: *)
Capacitor, Ceramic (MLCC), 10uF, ±10%, 6.3V, X5R, ±10%, SMD 0603; Manufacturer: Taiyo Yuden; Manufacturer Part Number: JMK107BJ106KA-T
footprint CAP-0603 (0603 (1608M) Capacitor)
pins: 1, 2

## JMK107BJ106MA-T
designator C?  Capacitance: 10uF  (hidden comment: *)
Capacitor, Ceramic (MLCC), 10uF, ±20%, 6.3V, X5R, ±20%, SMD 0603; Manufacturer: Taiyo Yuden; Manufacturer Part Number: JMK107BJ106MA-T
footprint CAP-0603 (0603 (1608M) Capacitor)
pins: 1, 2

## JMK107BJ225KA-T
designator C?  Capacitance: 2.2uF  (hidden comment: *)
Capacitor, Ceramic (MLCC), 2.2uF, ±10%, 6.3V, X5R, ±10%, SMD 0603; Manufacturer: Taiyo Yuden; Manufacturer Part Number: JMK107BJ225KA-T
footprint CAP-0603 (0603 (1608M) Capacitor)
pins: 1, 2

## JMK107BJ226MA-TD
designator C?  Capacitance: 22uF  (hidden comment: *)
Capacitor, Ceramic (MLCC), 22uF, ±20%, 6.3V, X5R, ±20%, SMD 0603; Manufacturer: Taiyo Yuden; Manufacturer Part Number: JMK107BJ226MA-TD
footprint CAP-0603 (0603 (1608M) Capacitor)
pins: 1, 2

## JMK107BJ475KA-T
designator C?  Capacitance: 4.7uF  (hidden comment: *)
Capacitor, Ceramic (MLCC), 4.7uF, ±10%, 6.3V, X5R, ±10%, SMD 0603; Manufacturer: Taiyo Yuden; Manufacturer Part Number: JMK107BJ475KA-T
footprint CAP-0603 (0603 (1608M) Capacitor)
pins: 1, 2

## JMK107BJ475MA-T
designator C?  Capacitance: 4.7uF  (hidden comment: *)
Capacitor, Ceramic (MLCC), 4.7uF, ±20%, 6.3V, X5R, ±20%, SMD 0603; Manufacturer: Taiyo Yuden; Manufacturer Part Number: JMK107BJ475MA-T
footprint CAP-0603 (0603 (1608M) Capacitor)
pins: 1, 2

## JMK107C6475MA-T
designator C?  Capacitance: 4.7uF  (hidden comment: *)
Capacitor, Ceramic (MLCC), 4.7uF, ±20%, 6.3V, X6S, ±20%, SMD 0603; Manufacturer: Taiyo Yuden; Manufacturer Part Number: JMK107C6475MA-T
footprint CAP-0603 (0603 (1608M) Capacitor)
pins: 1, 2

## LDK107BBJ226MA-T
designator C?  Capacitance: 22uF  (hidden comment: *)
Capacitor, Ceramic (MLCC), 22uF, ±20%, 10V, X5R, ±20%, SMD 0603; Manufacturer: Taiyo Yuden; Manufacturer Part Number: LDK107BBJ226MA-T
footprint CAP-0603 (0603 (1608M) Capacitor)
pins: 1, 2

## LMK107B7105KA-T
designator C?  Capacitance: 1uF  (hidden comment: *)
Capacitor, Ceramic (MLCC), 1uF, ±10%, 10V, X7R, ±10%, SMD 0603; Manufacturer: Taiyo Yuden; Manufacturer Part Number: LMK107B7105KA-T
footprint CAP-0603 (0603 (1608M) Capacitor)
pins: 1, 2

## LMK107B7105KAHT
designator C?  Capacitance: 1uF  (hidden comment: *)
Capacitor, Ceramic (MLCC), 1uF, ±10%, 10V, X7R, ±10%, SMD 0603; Manufacturer: Taiyo Yuden; Manufacturer Part Number: LMK107B7105KAHT
footprint CAP-0603 (0603 (1608M) Capacitor)
pins: 1, 2

## LMK107B7224KA-T
designator C?  Capacitance: 220nF  (hidden comment: *)
Capacitor, Ceramic (MLCC), 220nF, ±10%, 10V, X7R, ±10%, SMD 0603; Manufacturer: Taiyo Yuden; Manufacturer Part Number: LMK107B7224KA-T
footprint CAP-0603 (0603 (1608M) Capacitor)
pins: 1, 2

## LMK107B7225KA-T
designator C?  Capacitance: 2.2uF  (hidden comment: *)
Capacitor, Ceramic (MLCC), 2.2uF, ±10%, 10V, X7R, ±10%, SMD 0603; Manufacturer: Taiyo Yuden; Manufacturer Part Number: LMK107B7225KA-T
footprint CAP-0603 (0603 (1608M) Capacitor)
pins: 1, 2

## LMK107B7225KA-TR
designator C?  Capacitance: 2.2uF  (hidden comment: *)
Capacitor, Ceramic (MLCC), 2.2uF, ±10%, 10V, X7R, ±10%, SMD 0603; Manufacturer: Taiyo Yuden; Manufacturer Part Number: LMK107B7225KA-TR
footprint CAP-0603 (0603 (1608M) Capacitor)
pins: 1, 2

## LMK107BJ105KA-T
designator C?  Capacitance: 1uF  (hidden comment: *)
Capacitor, Ceramic (MLCC), 1uF, ±10%, 10V, X5R, ±10%, SMD 0603; Manufacturer: Taiyo Yuden; Manufacturer Part Number: LMK107BJ105KA-T
footprint CAP-0603 (0603 (1608M) Capacitor)
pins: 1, 2

## LMK107BJ106MALTD
designator C?  Capacitance: 10uF  (hidden comment: *)
Capacitor, Ceramic (MLCC), 10uF, ±20%, 10V, X5R, ±20%, SMD 0603; Manufacturer: Taiyo Yuden; Manufacturer Part Number: LMK107BJ106MALTD
footprint CAP-0603 (0603 (1608M) Capacitor)
pins: 1, 2

## LMK107BJ225KA-T
designator C?  Capacitance: 2.2uF  (hidden comment: *)
Capacitor, Ceramic (MLCC), 2.2uF, ±10%, 10V, X5R, ±10%, SMD 0603; Manufacturer: Taiyo Yuden; Manufacturer Part Number: LMK107BJ225KA-T
footprint CAP-0603 (0603 (1608M) Capacitor)
pins: 1, 2

## LMK107BJ225KAHT
designator C?  Capacitance: 2.2uF  (hidden comment: *)
Capacitor, Ceramic (MLCC), 2.2uF, ±10%, 10V, X5R, ±10%, SMD 0603; Manufacturer: Taiyo Yuden; Manufacturer Part Number: LMK107BJ225KAHT
footprint CAP-0603 (0603 (1608M) Capacitor)
pins: 1, 2

## LMK107BJ225MA-T
designator C?  Capacitance: 2.2uF  (hidden comment: *)
Capacitor, Ceramic (MLCC), 2.2uF, ±20%, 10V, X5R, ±20%, SMD 0603; Manufacturer: Taiyo Yuden; Manufacturer Part Number: LMK107BJ225MA-T
footprint CAP-0603 (0603 (1608M) Capacitor)
pins: 1, 2

## LMK107BJ475KA-T
designator C?  Capacitance: 4.7uF  (hidden comment: *)
Capacitor, Ceramic (MLCC), 4.7uF, ±10%, 10V, X5R, ±10%, SMD 0603; Manufacturer: Taiyo Yuden; Manufacturer Part Number: LMK107BJ475KA-T
footprint CAP-0603 (0603 (1608M) Capacitor)
pins: 1, 2

## LMK107BJ475KAHT
designator C?  Capacitance: 4.7uF  (hidden comment: *)
Capacitor, Ceramic (MLCC), 4.7uF, ±10%, 10V, X5R, ±10%, SMD 0603; Manufacturer: Taiyo Yuden; Manufacturer Part Number: LMK107BJ475KAHT
footprint CAP-0603 (0603 (1608M) Capacitor)
pins: 1, 2

## MG18B104K500CT
designator C?  Capacitance: 100nF  (hidden comment: *)
Capacitor, Ceramic (MLCC), 100nF, ±10%, 50V, X7R, ±10%, SMD 0603; Manufacturer: Walsin Tech Corp; Manufacturer Part Number: MG18B104K500CT
footprint CAP-0603 (0603 (1608M) Capacitor)
pins: 1, 2

## MT18B102K101CT
designator C?  Capacitance: 1nF  (hidden comment: *)
Capacitor, Ceramic (MLCC), 1nF, ±10%, 100V, X7R, ±10%, SMD 0603; Manufacturer: Walsin Tech Corp; Manufacturer Part Number: MT18B102K101CT
footprint CAP-0603 (0603 (1608M) Capacitor)
pins: 1, 2

## MT18B102K500CT
designator C?  Capacitance: 1nF  (hidden comment: *)
Capacitor, Ceramic (MLCC), 1nF, ±10%, 50V, X7R, ±10%, SMD 0603; Manufacturer: Walsin Tech Corp; Manufacturer Part Number: MT18B102K500CT
footprint CAP-0603 (0603 (1608M) Capacitor)
pins: 1, 2

## MT18B103K250CT
designator C?  Capacitance: 10nF  (hidden comment: *)
Capacitor, Ceramic (MLCC), 10nF, ±10%, 25V, X7R, ±10%, SMD 0603; Manufacturer: Walsin Tech Corp; Manufacturer Part Number: MT18B103K250CT
footprint CAP-0603 (0603 (1608M) Capacitor)
pins: 1, 2

## MT18B103K500CT
designator C?  Capacitance: 10nF  (hidden comment: *)
Capacitor, Ceramic (MLCC), 10nF, ±10%, 50V, X7R, ±10%, SMD 0603; Manufacturer: Walsin Tech Corp; Manufacturer Part Number: MT18B103K500CT
footprint CAP-0603 (0603 (1608M) Capacitor)
pins: 1, 2

## MT18B104K160CT
designator C?  Capacitance: 100nF  (hidden comment: *)
Capacitor, Ceramic (MLCC), 100nF, ±10%, 16V, X7R, ±10%, SMD 0603; Manufacturer: Walsin Tech Corp; Manufacturer Part Number: MT18B104K160CT
footprint CAP-0603 (0603 (1608M) Capacitor)
pins: 1, 2

## MT18B104K500CT
designator C?  Capacitance: 100nF  (hidden comment: *)
Capacitor, Ceramic (MLCC), 100nF, ±10%, 50V, X7R, ±10%, SMD 0603; Manufacturer: Walsin Tech Corp; Manufacturer Part Number: MT18B104K500CT
footprint CAP-0603 (0603 (1608M) Capacitor)
pins: 1, 2

## MT18B221K500CT
designator C?  Capacitance: 220pF  (hidden comment: *)
Capacitor, Ceramic (MLCC), 220pF, ±10%, 50V, X7R, ±10%, SMD 0603; Manufacturer: Walsin Tech Corp; Manufacturer Part Number: MT18B221K500CT
footprint CAP-0603 (0603 (1608M) Capacitor)
pins: 1, 2

## MT18B222K500CT
designator C?  Capacitance: 2.2nF  (hidden comment: *)
Capacitor, Ceramic (MLCC), 2.2nF, ±10%, 50V, X7R, ±10%, SMD 0603; Manufacturer: Walsin Tech Corp; Manufacturer Part Number: MT18B222K500CT
footprint CAP-0603 (0603 (1608M) Capacitor)
pins: 1, 2

## MT18B223K500CT
designator C?  Capacitance: 22nF  (hidden comment: *)
Capacitor, Ceramic (MLCC), 22nF, ±10%, 50V, X7R, ±10%, SMD 0603; Manufacturer: Walsin Tech Corp; Manufacturer Part Number: MT18B223K500CT
footprint CAP-0603 (0603 (1608M) Capacitor)
pins: 1, 2

## MT18B332K250CT
designator C?  Capacitance: 3.3nF  (hidden comment: *)
Capacitor, Ceramic (MLCC), 3.3nF, ±10%, 25V, X7R, ±10%, SMD 0603; Manufacturer: Walsin Tech Corp; Manufacturer Part Number: MT18B332K250CT
footprint CAP-0603 (0603 (1608M) Capacitor)
pins: 1, 2

## MT18B332K500CT
designator C?  Capacitance: 3.3nF  (hidden comment: *)
Capacitor, Ceramic (MLCC), 3.3nF, ±10%, 50V, X7R, ±10%, SMD 0603; Manufacturer: Walsin Tech Corp; Manufacturer Part Number: MT18B332K500CT
footprint CAP-0603 (0603 (1608M) Capacitor)
pins: 1, 2

## MT18B333K500CT
designator C?  Capacitance: 33nF  (hidden comment: *)
Capacitor, Ceramic (MLCC), 33nF, ±10%, 50V, X7R, ±10%, SMD 0603; Manufacturer: Walsin Tech Corp; Manufacturer Part Number: MT18B333K500CT
footprint CAP-0603 (0603 (1608M) Capacitor)
pins: 1, 2

## MT18B472K101CT
designator C?  Capacitance: 4.7nF  (hidden comment: *)
Capacitor, Ceramic (MLCC), 4.7nF, ±10%, 100V, X7R, ±10%, SMD 0603; Manufacturer: Walsin Tech Corp; Manufacturer Part Number: MT18B472K101CT
footprint CAP-0603 (0603 (1608M) Capacitor)
pins: 1, 2

## MT18B473K500CT
designator C?  Capacitance: 47nF  (hidden comment: *)
Capacitor, Ceramic (MLCC), 47nF, ±10%, 50V, X7R, ±10%, SMD 0603; Manufacturer: Walsin Tech Corp; Manufacturer Part Number: MT18B473K500CT
footprint CAP-0603 (0603 (1608M) Capacitor)
pins: 1, 2

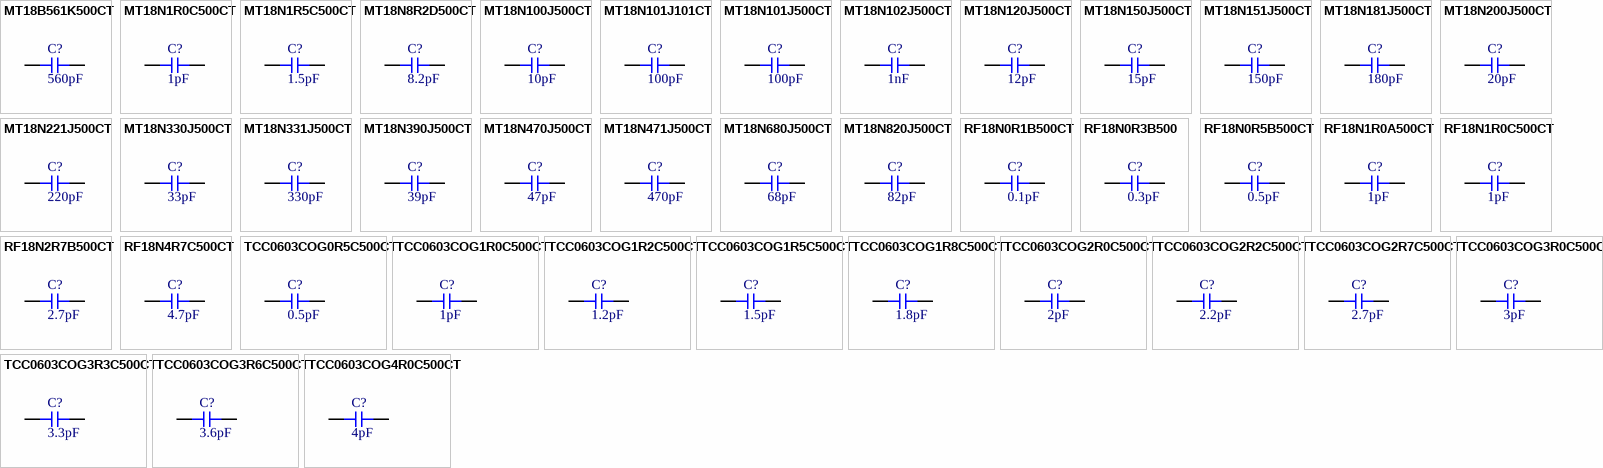
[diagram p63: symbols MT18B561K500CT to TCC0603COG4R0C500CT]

## MT18B561K500CT
designator C?  Capacitance: 560pF  (hidden comment: *)
Capacitor, Ceramic (MLCC), 560pF, ±10%, 50V, X7R, ±10%, SMD 0603; Manufacturer: Walsin Tech Corp; Manufacturer Part Number: MT18B561K500CT
footprint CAP-0603 (0603 (1608M) Capacitor)
pins: 1, 2

## MT18N1R0C500CT
designator C?  Capacitance: 1pF  (hidden comment: *)
Capacitor, Ceramic (MLCC), 1pF, ±0.25pF, 50V, NP0, ±0.25pF, SMD 0603; Manufacturer: Walsin Tech Corp; Manufacturer Part Number: MT18N1R0C500CT
footprint CAP-0603 (0603 (1608M) Capacitor)
pins: 1, 2

## MT18N1R5C500CT
designator C?  Capacitance: 1.5pF  (hidden comment: *)
Capacitor, Ceramic (MLCC), 1.5pF, ±0.25pF, 50V, NP0, ±0.25pF, SMD 0603; Manufacturer: Walsin Tech Corp; Manufacturer Part Number: MT18N1R5C500CT
footprint CAP-0603 (0603 (1608M) Capacitor)
pins: 1, 2

## MT18N8R2D500CT
designator C?  Capacitance: 8.2pF  (hidden comment: *)
Capacitor, Ceramic (MLCC), 8.2pF, ±0.5pF, 50V, NP0, ±0.5pF, SMD 0603; Manufacturer: Walsin Tech Corp; Manufacturer Part Number: MT18N8R2D500CT
footprint CAP-0603 (0603 (1608M) Capacitor)
pins: 1, 2

## MT18N100J500CT
designator C?  Capacitance: 10pF  (hidden comment: *)
Capacitor, Ceramic (MLCC), 10pF, ±5%, 50V, NP0, ±5%, SMD 0603; Manufacturer: Walsin Tech Corp; Manufacturer Part Number: MT18N100J500CT
footprint CAP-0603 (0603 (1608M) Capacitor)
pins: 1, 2

## MT18N101J101CT
designator C?  Capacitance: 100pF  (hidden comment: *)
Capacitor, Ceramic (MLCC), 100pF, ±5%, 100V, NP0, ±5%, SMD 0603; Manufacturer: Walsin Tech Corp; Manufacturer Part Number: MT18N101J101CT
footprint CAP-0603 (0603 (1608M) Capacitor)
pins: 1, 2

## MT18N101J500CT
designator C?  Capacitance: 100pF  (hidden comment: *)
Capacitor, Ceramic (MLCC), 100pF, ±5%, 50V, NP0, ±5%, SMD 0603; Manufacturer: Walsin Tech Corp; Manufacturer Part Number: MT18N101J500CT
footprint CAP-0603 (0603 (1608M) Capacitor)
pins: 1, 2

## MT18N102J500CT
designator C?  Capacitance: 1nF  (hidden comment: *)
Capacitor, Ceramic (MLCC), 1nF, ±5%, 50V, NP0, ±5%, SMD 0603; Manufacturer: Walsin Tech Corp; Manufacturer Part Number: MT18N102J500CT
footprint CAP-0603 (0603 (1608M) Capacitor)
pins: 1, 2

## MT18N120J500CT
designator C?  Capacitance: 12pF  (hidden comment: *)
Capacitor, Ceramic (MLCC), 12pF, ±5%, 50V, NP0, ±5%, SMD 0603; Manufacturer: Walsin Tech Corp; Manufacturer Part Number: MT18N120J500CT
footprint CAP-0603 (0603 (1608M) Capacitor)
pins: 1, 2

## MT18N150J500CT
designator C?  Capacitance: 15pF  (hidden comment: *)
Capacitor, Ceramic (MLCC), 15pF, ±5%, 50V, NP0, ±5%, SMD 0603; Manufacturer: Walsin Tech Corp; Manufacturer Part Number: MT18N150J500CT
footprint CAP-0603 (0603 (1608M) Capacitor)
pins: 1, 2

## MT18N151J500CT
designator C?  Capacitance: 150pF  (hidden comment: *)
Capacitor, Ceramic (MLCC), 150pF, ±5%, 50V, NP0, ±5%, SMD 0603; Manufacturer: Walsin Tech Corp; Manufacturer Part Number: MT18N151J500CT
footprint CAP-0603 (0603 (1608M) Capacitor)
pins: 1, 2

## MT18N181J500CT
designator C?  Capacitance: 180pF  (hidden comment: *)
Capacitor, Ceramic (MLCC), 180pF, ±5%, 50V, NP0, ±5%, SMD 0603; Manufacturer: Walsin Tech Corp; Manufacturer Part Number: MT18N181J500CT
footprint CAP-0603 (0603 (1608M) Capacitor)
pins: 1, 2

## MT18N200J500CT
designator C?  Capacitance: 20pF  (hidden comment: *)
Capacitor, Ceramic (MLCC), 20pF, ±5%, 50V, NP0, ±5%, SMD 0603; Manufacturer: Walsin Tech Corp; Manufacturer Part Number: MT18N200J500CT
footprint CAP-0603 (0603 (1608M) Capacitor)
pins: 1, 2

## MT18N221J500CT
designator C?  Capacitance: 220pF  (hidden comment: *)
Capacitor, Ceramic (MLCC), 220pF, ±5%, 50V, NP0, ±5%, SMD 0603; Manufacturer: Walsin Tech Corp; Manufacturer Part Number: MT18N221J500CT
footprint CAP-0603 (0603 (1608M) Capacitor)
pins: 1, 2

## MT18N330J500CT
designator C?  Capacitance: 33pF  (hidden comment: *)
Capacitor, Ceramic (MLCC), 33pF, ±5%, 50V, NP0, ±5%, SMD 0603; Manufacturer: Walsin Tech Corp; Manufacturer Part Number: MT18N330J500CT
footprint CAP-0603 (0603 (1608M) Capacitor)
pins: 1, 2

## MT18N331J500CT
designator C?  Capacitance: 330pF  (hidden comment: *)
Capacitor, Ceramic (MLCC), 330pF, ±5%, 50V, NP0, ±5%, SMD 0603; Manufacturer: Walsin Tech Corp; Manufacturer Part Number: MT18N331J500CT
footprint CAP-0603 (0603 (1608M) Capacitor)
pins: 1, 2

## MT18N390J500CT
designator C?  Capacitance: 39pF  (hidden comment: *)
Capacitor, Ceramic (MLCC), 39pF, ±5%, 50V, NP0, ±5%, SMD 0603; Manufacturer: Walsin Tech Corp; Manufacturer Part Number: MT18N390J500CT
footprint CAP-0603 (0603 (1608M) Capacitor)
pins: 1, 2

## MT18N470J500CT
designator C?  Capacitance: 47pF  (hidden comment: *)
Capacitor, Ceramic (MLCC), 47pF, ±5%, 50V, NP0, ±5%, SMD 0603; Manufacturer: Walsin Tech Corp; Manufacturer Part Number: MT18N470J500CT
footprint CAP-0603 (0603 (1608M) Capacitor)
pins: 1, 2

## MT18N471J500CT
designator C?  Capacitance: 470pF  (hidden comment: *)
Capacitor, Ceramic (MLCC), 470pF, ±5%, 50V, NP0, ±5%, SMD 0603; Manufacturer: Walsin Tech Corp; Manufacturer Part Number: MT18N471J500CT
footprint CAP-0603 (0603 (1608M) Capacitor)
pins: 1, 2

## MT18N680J500CT
designator C?  Capacitance: 68pF  (hidden comment: *)
Capacitor, Ceramic (MLCC), 68pF, ±5%, 50V, NP0, ±5%, SMD 0603; Manufacturer: Walsin Tech Corp; Manufacturer Part Number: MT18N680J500CT
footprint CAP-0603 (0603 (1608M) Capacitor)
pins: 1, 2

## MT18N820J500CT
designator C?  Capacitance: 82pF  (hidden comment: *)
Capacitor, Ceramic (MLCC), 82pF, ±5%, 50V, NP0, ±5%, SMD 0603; Manufacturer: Walsin Tech Corp; Manufacturer Part Number: MT18N820J500CT
footprint CAP-0603 (0603 (1608M) Capacitor)
pins: 1, 2

## RF18N0R1B500CT
designator C?  Capacitance: 0.1pF  (hidden comment: *)
Capacitor, Ceramic (MLCC), 0.1pF, ±0.1pF, 50V, NP0, ±0.1pF, SMD 0603; Manufacturer: Walsin Tech Corp; Manufacturer Part Number: RF18N0R1B500CT
footprint CAP-0603 (0603 (1608M) Capacitor)
pins: 1, 2

## RF18N0R3B500
designator C?  Capacitance: 0.3pF  (hidden comment: *)
Capacitor, Ceramic (MLCC), 0.3pF, ±0.1pF, 50V, NP0, ±0.1pF, SMD 0603; Manufacturer: Walsin Tech Corp; Manufacturer Part Number: RF18N0R3B500
footprint CAP-0603 (0603 (1608M) Capacitor)
pins: 1, 2

## RF18N0R5B500CT
designator C?  Capacitance: 0.5pF  (hidden comment: *)
Capacitor, Ceramic (MLCC), 0.5pF, ±0.1pF, 50V, NP0, ±0.1pF, SMD 0603; Manufacturer: Walsin Tech Corp; Manufacturer Part Number: RF18N0R5B500CT
footprint CAP-0603 (0603 (1608M) Capacitor)
pins: 1, 2

## RF18N1R0A500CT
designator C?  Capacitance: 1pF  (hidden comment: *)
Capacitor, Ceramic (MLCC), 1pF, ±0.05pF, 50V, NP0, ±0.05pF, SMD 0603; Manufacturer: Walsin Tech Corp; Manufacturer Part Number: RF18N1R0A500CT
footprint CAP-0603 (0603 (1608M) Capacitor)
pins: 1, 2

## RF18N1R0C500CT
designator C?  Capacitance: 1pF  (hidden comment: *)
Capacitor, Ceramic (MLCC), 1pF, ±0.25pF, 50V, NP0, ±0.25pF, SMD 0603; Manufacturer: Walsin Tech Corp; Manufacturer Part Number: RF18N1R0C500CT
footprint CAP-0603 (0603 (1608M) Capacitor)
pins: 1, 2

## RF18N2R7B500CT
designator C?  Capacitance: 2.7pF  (hidden comment: *)
Capacitor, Ceramic (MLCC), 2.7pF, ±0.1pF, 50V, NP0, ±0.1pF, SMD 0603; Manufacturer: Walsin Tech Corp; Manufacturer Part Number: RF18N2R7B500CT
footprint CAP-0603 (0603 (1608M) Capacitor)
pins: 1, 2

## RF18N4R7C500CT
designator C?  Capacitance: 4.7pF  (hidden comment: *)
Capacitor, Ceramic (MLCC), 4.7pF, ±0.25pF, 50V, NP0, ±0.25pF, SMD 0603; Manufacturer: Walsin Tech Corp; Manufacturer Part Number: RF18N4R7C500CT
footprint CAP-0603 (0603 (1608M) Capacitor)
pins: 1, 2

## TCC0603COG0R5C500CT
designator C?  Capacitance: 0.5pF  (hidden comment: *)
Capacitor, Ceramic (MLCC), 0.5pF, ±0.25pF, 50V, C0G, ±0.25pF, SMD 0603; Manufacturer: CCTC; Manufacturer Part Number: TCC0603COG0R5C500CT
footprint CAP-0603 (0603 (1608M) Capacitor)
pins: 1, 2

## TCC0603COG1R0C500CT
designator C?  Capacitance: 1pF  (hidden comment: *)
Capacitor, Ceramic (MLCC), 1pF, ±0.25pF, 50V, C0G, ±0.25pF, SMD 0603; Manufacturer: CCTC; Manufacturer Part Number: TCC0603COG1R0C500CT
footprint CAP-0603 (0603 (1608M) Capacitor)
pins: 1, 2

## TCC0603COG1R2C500CT
designator C?  Capacitance: 1.2pF  (hidden comment: *)
Capacitor, Ceramic (MLCC), 1.2pF, ±0.25pF, 50V, C0G, ±0.25pF, SMD 0603; Manufacturer: CCTC; Manufacturer Part Number: TCC0603COG1R2C500CT
footprint CAP-0603 (0603 (1608M) Capacitor)
pins: 1, 2

## TCC0603COG1R5C500CT
designator C?  Capacitance: 1.5pF  (hidden comment: *)
Capacitor, Ceramic (MLCC), 1.5pF, ±0.25pF, 50V, C0G, ±0.25pF, SMD 0603; Manufacturer: CCTC; Manufacturer Part Number: TCC0603COG1R5C500CT
footprint CAP-0603 (0603 (1608M) Capacitor)
pins: 1, 2

## TCC0603COG1R8C500CT
designator C?  Capacitance: 1.8pF  (hidden comment: *)
Capacitor, Ceramic (MLCC), 1.8pF, ±0.25pF, 50V, C0G, ±0.25pF, SMD 0603; Manufacturer: CCTC; Manufacturer Part Number: TCC0603COG1R8C500CT
footprint CAP-0603 (0603 (1608M) Capacitor)
pins: 1, 2

## TCC0603COG2R0C500CT
designator C?  Capacitance: 2pF  (hidden comment: *)
Capacitor, Ceramic (MLCC), 2pF, ±0.25pF, 50V, C0G, ±0.25pF, SMD 0603; Manufacturer: CCTC; Manufacturer Part Number: TCC0603COG2R0C500CT
footprint CAP-0603 (0603 (1608M) Capacitor)
pins: 1, 2

## TCC0603COG2R2C500CT
designator C?  Capacitance: 2.2pF  (hidden comment: *)
Capacitor, Ceramic (MLCC), 2.2pF, ±0.25pF, 50V, C0G, ±0.25pF, SMD 0603; Manufacturer: CCTC; Manufacturer Part Number: TCC0603COG2R2C500CT
footprint CAP-0603 (0603 (1608M) Capacitor)
pins: 1, 2

## TCC0603COG2R7C500CT
designator C?  Capacitance: 2.7pF  (hidden comment: *)
Capacitor, Ceramic (MLCC), 2.7pF, ±0.25pF, 50V, C0G, ±0.25pF, SMD 0603; Manufacturer: CCTC; Manufacturer Part Number: TCC0603COG2R7C500CT
footprint CAP-0603 (0603 (1608M) Capacitor)
pins: 1, 2

## TCC0603COG3R0C500CT
designator C?  Capacitance: 3pF  (hidden comment: *)
Capacitor, Ceramic (MLCC), 3pF, ±0.25pF, 50V, C0G, ±0.25pF, SMD 0603; Manufacturer: CCTC; Manufacturer Part Number: TCC0603COG3R0C500CT
footprint CAP-0603 (0603 (1608M) Capacitor)
pins: 1, 2

## TCC0603COG3R3C500CT
designator C?  Capacitance: 3.3pF  (hidden comment: *)
Capacitor, Ceramic (MLCC), 3.3pF, ±0.25pF, 50V, C0G, ±0.25pF, SMD 0603; Manufacturer: CCTC; Manufacturer Part Number: TCC0603COG3R3C500CT
footprint CAP-0603 (0603 (1608M) Capacitor)
pins: 1, 2

## TCC0603COG3R6C500CT
designator C?  Capacitance: 3.6pF  (hidden comment: *)
Capacitor, Ceramic (MLCC), 3.6pF, ±0.25pF, 50V, C0G, ±0.25pF, SMD 0603; Manufacturer: CCTC; Manufacturer Part Number: TCC0603COG3R6C500CT
footprint CAP-0603 (0603 (1608M) Capacitor)
pins: 1, 2

## TCC0603COG4R0C500CT
designator C?  Capacitance: 4pF  (hidden comment: *)
Capacitor, Ceramic (MLCC), 4pF, ±0.25pF, 50V, C0G, ±0.25pF, SMD 0603; Manufacturer: CCTC; Manufacturer Part Number: TCC0603COG4R0C500CT
footprint CAP-0603 (0603 (1608M) Capacitor)
pins: 1, 2

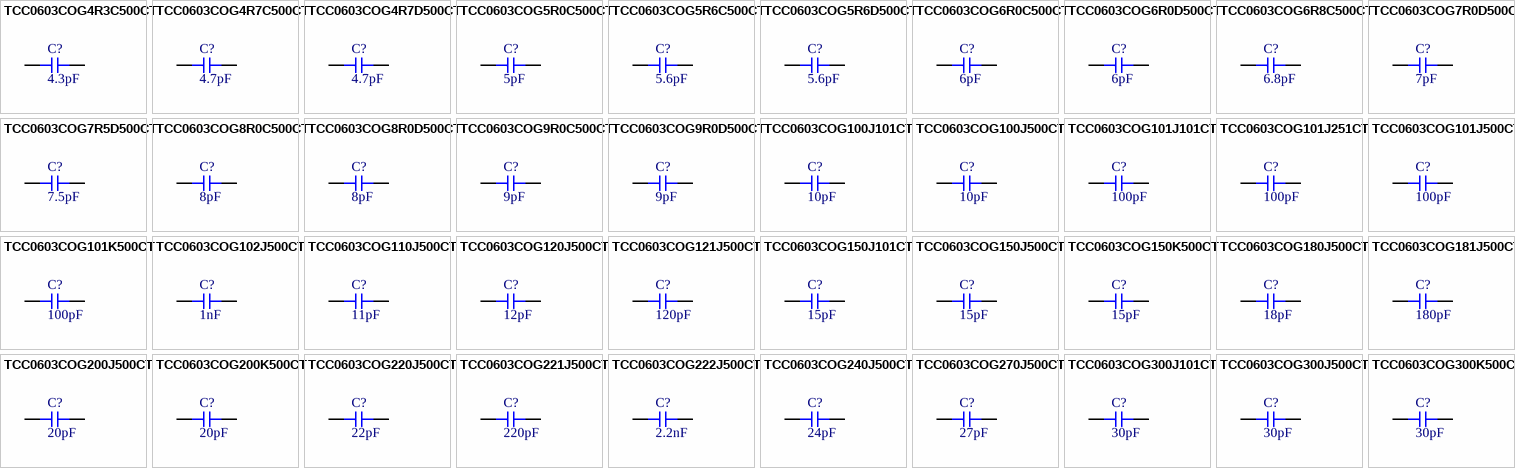
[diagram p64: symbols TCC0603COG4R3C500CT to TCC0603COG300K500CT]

## TCC0603COG4R3C500CT
designator C?  Capacitance: 4.3pF  (hidden comment: *)
Capacitor, Ceramic (MLCC), 4.3pF, ±0.25pF, 50V, C0G, ±0.25pF, SMD 0603; Manufacturer: CCTC; Manufacturer Part Number: TCC0603COG4R3C500CT
footprint CAP-0603 (0603 (1608M) Capacitor)
pins: 1, 2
